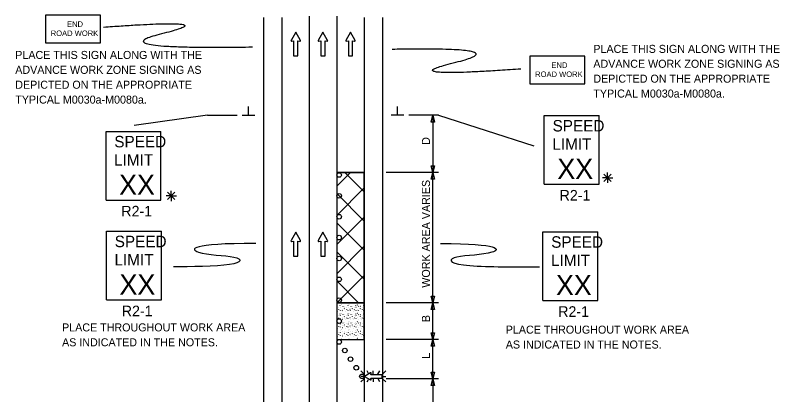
# Model space of a CAD drawing. Extents: x 16734 to 18479, y 5690 to 6925.
# Drawn here: x 16734 to 17402, y 6594 to 6925 of the extents above; entities that cross this region are included whole.
import ezdxf

# ---------------------------------------------------------------- set-up
doc = ezdxf.new("R2010")
doc.units = 0
for name, color, linetype in [('ALI_LEGAL_EX', 7, 'Continuous'), ('MT_SCRATCH_LEVEL_E', 7, 'Continuous'), ('PAVT_EDGE_EX', 7, 'Continuous'), ('TRAFFIC_SIGNS_PR', 7, 'Continuous'), ('TYPICAL_TEXT_DIMEN_PR', 7, 'Continuous')]:
    doc.layers.add(name, color=color, linetype=linetype)

msp = doc.modelspace()

# ---------------------------------------------------------------- linework, layer by layer
at = {"layer": 'ALI_LEGAL_EX'}
for p, q in [((16991.15, 6924.81), (16991.15, 6107.83)), ((17015.15, 6924.81), (17015.15, 6107.83))]:
    msp.add_line(p, q, dxfattribs=at)
for points in [[(16991.15, 6924.81), (16991.15, 6899.81)], [(17015.15, 6924.81), (17015.15, 6899.81)], [(16991.15, 6824.81), (16991.15, 6799.81)], [(17015.15, 6824.81), (17015.15, 6799.81)], [(16991.15, 6724.81), (16991.15, 6699.81)], [(17015.15, 6724.81), (17015.15, 6699.81)], [(16991.15, 6624.81), (16991.15, 6599.81)]]:
    msp.add_lwpolyline(points, dxfattribs=at)
at = {"layer": 'MT_SCRATCH_LEVEL_E'}
for p, q in [((16979.3, 6910.86), (16975.19, 6903.61)), ((16983.44, 6903.61), (16979.3, 6910.86)), ((17003, 6910.86), (16998.89, 6903.61)), ((17007.15, 6903.61), (17003, 6910.86)), ((17027.11, 6910.86), (17023, 6903.61)), ((17031.26, 6903.61), (17027.11, 6910.86)), ((16975.67, 6902.93), (16977.45, 6903.25)), ((16977.45, 6903.25), (16977.45, 6889.99)), ((16981.19, 6889.99), (16981.19, 6903.25)), ((16981.19, 6903.25), (16982.97, 6902.93)), ((16999.37, 6902.93), (17001.15, 6903.25)), ((17001.15, 6903.25), (17001.15, 6889.99)), ((17004.89, 6889.99), (17004.89, 6903.25)), ((17004.89, 6903.25), (17006.67, 6902.93)), ((17023.48, 6902.93), (17025.26, 6903.25)), ((17025.26, 6903.25), (17025.26, 6889.99)), ((17029, 6889.99), (17029, 6903.25)), ((17029, 6903.25), (17030.78, 6902.93)), ((16977.45, 6889.99), (16981.19, 6889.99)), ((17001.15, 6889.99), (17004.89, 6889.99)), ((17025.26, 6889.99), (17029, 6889.99)), ((16979.3, 6736.02), (16975.19, 6728.78)), ((16983.44, 6728.78), (16979.3, 6736.02)), ((17003, 6736.02), (16998.89, 6728.78)), ((17007.15, 6728.78), (17003, 6736.02)), ((16975.67, 6728.09), (16977.45, 6728.41)), ((16977.45, 6728.41), (16977.45, 6715.15)), ((16981.19, 6715.15), (16981.19, 6728.41)), ((16981.19, 6728.41), (16982.97, 6728.09)), ((16999.37, 6728.09), (17001.15, 6728.41)), ((17001.15, 6728.41), (17001.15, 6715.15)), ((17004.89, 6715.15), (17004.89, 6728.41)), ((17004.89, 6728.41), (17006.67, 6728.09)), ((16977.45, 6715.15), (16981.19, 6715.15)), ((17001.15, 6715.15), (17004.89, 6715.15))]:
    msp.add_line(p, q, dxfattribs=at)
for centre, start, end in [((16975.59, 6903.39), 150.42484, 279.96381), ((16983.04, 6903.39), 260.03619, 29.77312), ((16999.3, 6903.39), 150.42484, 279.96381), ((17006.74, 6903.39), 260.03619, 29.77312), ((17023.41, 6903.39), 150.42484, 279.96381), ((17030.85, 6903.39), 260.03619, 29.77312), ((16975.59, 6728.55), 150.42484, 279.96381), ((16983.04, 6728.55), 260.03619, 29.77312), ((16999.3, 6728.55), 150.42484, 279.96381), ((17006.74, 6728.55), 260.03619, 29.77312)]:
    msp.add_arc(centre, 0.463, start, end, dxfattribs=at)
at = {"layer": 'PAVT_EDGE_EX'}
for p, q in [((16951.15, 6923.54), (16951.15, 6107.83)), ((16967.15, 6923.54), (16967.15, 6107.83)), ((17039.15, 6923.54), (17039.15, 6107.83)), ((17055.15, 6923.54), (17055.15, 6107.83)), ((17039.15, 6788.15), (17015.15, 6788.15)), ((17015.15, 6788.15), (17039.15, 6788.15)), ((17015.15, 6776.25), (17027.06, 6788.15)), ((17039.15, 6771.35), (17022.34, 6788.15)), ((17039.15, 6674.43), (17039.15, 6788.15)), ((17015.15, 6750.8), (17039.15, 6774.8)), ((17039.15, 6745.89), (17015.15, 6769.89)), ((17015.15, 6725.34), (17039.15, 6749.34)), ((17039.15, 6720.43), (17015.15, 6744.43)), ((17015.15, 6699.89), (17039.15, 6723.89)), ((17039.15, 6694.98), (17015.15, 6718.98)), ((17015.15, 6674.43), (17039.15, 6698.43)), ((17034.24, 6674.43), (17015.15, 6693.52)), ((17015.15, 6674.43), (17039.15, 6674.43)), ((17015.15, 6674.43), (17039.15, 6674.43)), ((17039.15, 6674.43), (17015.15, 6674.43)), ((17015.15, 6674.43), (17015.15, 6674.43)), ((17016.08, 6674.07), (17016.13, 6674.19)), ((17016.65, 6670.75), (17016.7, 6670.67)), ((17016.7, 6668.54), (17016.75, 6668.46)), ((17018.1, 6671.88), (17018.15, 6671.99)), ((17018.18, 6670.61), (17018.23, 6670.53)), ((17018.86, 6672.84), (17018.92, 6672.76)), ((17019.6, 6672.81), (17019.65, 6672.73)), ((17019.82, 6668.82), (17019.87, 6668.94)), ((17020.47, 6671.43), (17020.52, 6671.35)), ((17021.75, 6669.69), (17021.8, 6669.61)), ((17021.92, 6671.58), (17021.97, 6671.69)), ((17022.97, 6674.07), (17023.02, 6674.19)), ((17023.54, 6670.75), (17023.59, 6670.67)), ((17023.59, 6668.54), (17023.64, 6668.46)), ((17024.99, 6671.88), (17025.04, 6671.99)), ((17025.07, 6670.61), (17025.12, 6670.53)), ((17025.75, 6672.84), (17025.8, 6672.76)), ((17026.49, 6672.81), (17026.54, 6672.73)), ((17026.71, 6668.82), (17026.76, 6668.94)), ((17027.36, 6671.43), (17027.41, 6671.35)), ((17028.64, 6669.69), (17028.69, 6669.61)), ((17028.81, 6671.58), (17028.86, 6671.69)), ((17029.85, 6674.07), (17029.91, 6674.19)), ((17030.42, 6670.75), (17030.48, 6670.67)), ((17030.47, 6668.54), (17030.53, 6668.46)), ((17031.88, 6671.88), (17031.93, 6671.99)), ((17031.96, 6670.61), (17032.01, 6670.53)), ((17032.64, 6672.84), (17032.69, 6672.76)), ((17033.38, 6672.81), (17033.43, 6672.73)), ((17033.6, 6668.82), (17033.65, 6668.94)), ((17034.24, 6671.43), (17034.3, 6671.35)), ((17035.52, 6669.69), (17035.57, 6669.61)), ((17035.69, 6671.58), (17035.75, 6671.69)), ((17036.74, 6674.07), (17036.8, 6674.19)), ((17037.31, 6670.75), (17037.36, 6670.67)), ((17037.36, 6668.54), (17037.41, 6668.46)), ((17038.76, 6671.88), (17038.81, 6671.99)), ((17038.84, 6670.61), (17038.89, 6670.53)), ((17039.15, 6642.37), (17039.15, 6674.43)), ((17016.08, 6666.79), (17016.13, 6666.9)), ((17016.65, 6663.46), (17016.7, 6663.39)), ((17017.98, 6667.96), (17017.99, 6667.85)), ((17018.1, 6664.59), (17018.15, 6664.71)), ((17018.18, 6663.32), (17018.23, 6663.25)), ((17018.86, 6665.55), (17018.92, 6665.47)), ((17019.6, 6665.52), (17019.65, 6665.44)), ((17020.01, 6667.62), (17020.06, 6667.54)), ((17020.47, 6664.14), (17020.52, 6664.06)), ((17021.75, 6662.4), (17021.8, 6662.33)), ((17021.79, 6668.29), (17021.84, 6668.4)), ((17021.92, 6664.29), (17021.97, 6664.41)), ((17022.97, 6666.79), (17023.02, 6666.9)), ((17023.54, 6663.46), (17023.59, 6663.39)), ((17024.87, 6667.96), (17024.88, 6667.85)), ((17024.99, 6664.59), (17025.04, 6664.71)), ((17025.07, 6663.32), (17025.12, 6663.25)), ((17025.75, 6665.55), (17025.8, 6665.47)), ((17026.49, 6665.52), (17026.54, 6665.44)), ((17026.9, 6667.62), (17026.95, 6667.54)), ((17027.36, 6664.14), (17027.41, 6664.06)), ((17028.64, 6662.4), (17028.69, 6662.33)), ((17028.68, 6668.29), (17028.73, 6668.4)), ((17028.81, 6664.29), (17028.86, 6664.41)), ((17029.85, 6666.79), (17029.91, 6666.9)), ((17030.42, 6663.46), (17030.48, 6663.39)), ((17031.76, 6667.96), (17031.77, 6667.85)), ((17031.88, 6664.59), (17031.93, 6664.71)), ((17031.96, 6663.32), (17032.01, 6663.25)), ((17032.64, 6665.55), (17032.69, 6665.47)), ((17033.38, 6665.52), (17033.43, 6665.44)), ((17033.78, 6667.62), (17033.84, 6667.54)), ((17034.24, 6664.14), (17034.3, 6664.06)), ((17035.52, 6662.4), (17035.57, 6662.33)), ((17035.56, 6668.29), (17035.62, 6668.4)), ((17035.69, 6664.29), (17035.75, 6664.41)), ((17036.74, 6666.79), (17036.8, 6666.9)), ((17037.31, 6663.46), (17037.36, 6663.39)), ((17038.64, 6667.96), (17038.66, 6667.85)), ((17038.76, 6664.59), (17038.81, 6664.71)), ((17038.84, 6663.32), (17038.89, 6663.25)), ((17016.08, 6659.5), (17016.13, 6659.62)), ((17016.65, 6656.18), (17016.7, 6656.1)), ((17016.7, 6661.26), (17016.75, 6661.18)), ((17017.98, 6660.68), (17017.99, 6660.56)), ((17018.1, 6657.31), (17018.15, 6657.42)), ((17018.18, 6656.04), (17018.23, 6655.96)), ((17018.86, 6658.27), (17018.92, 6658.19)), ((17019.6, 6658.24), (17019.65, 6658.16)), ((17019.82, 6661.53), (17019.87, 6661.65)), ((17020.01, 6660.34), (17020.06, 6660.26)), ((17020.47, 6656.86), (17020.52, 6656.78)), ((17021.79, 6661), (17021.84, 6661.12)), ((17021.92, 6657.01), (17021.97, 6657.12)), ((17022.97, 6659.5), (17023.02, 6659.62)), ((17023.54, 6656.18), (17023.59, 6656.1)), ((17023.59, 6661.26), (17023.64, 6661.18)), ((17024.87, 6660.68), (17024.88, 6660.56)), ((17024.99, 6657.31), (17025.04, 6657.42)), ((17025.07, 6656.04), (17025.12, 6655.96)), ((17025.75, 6658.27), (17025.8, 6658.19)), ((17026.49, 6658.24), (17026.54, 6658.16)), ((17026.71, 6661.53), (17026.76, 6661.65)), ((17026.9, 6660.34), (17026.95, 6660.26)), ((17027.36, 6656.86), (17027.41, 6656.78)), ((17028.68, 6661), (17028.73, 6661.12)), ((17028.81, 6657.01), (17028.86, 6657.12)), ((17029.85, 6659.5), (17029.91, 6659.62)), ((17030.42, 6656.18), (17030.48, 6656.1)), ((17030.47, 6661.26), (17030.53, 6661.18)), ((17031.76, 6660.68), (17031.77, 6660.56)), ((17031.88, 6657.31), (17031.93, 6657.42)), ((17031.96, 6656.04), (17032.01, 6655.96)), ((17032.64, 6658.27), (17032.69, 6658.19)), ((17033.38, 6658.24), (17033.43, 6658.16)), ((17033.6, 6661.53), (17033.65, 6661.65)), ((17033.78, 6660.34), (17033.84, 6660.26)), ((17034.24, 6656.86), (17034.3, 6656.78)), ((17035.56, 6661), (17035.62, 6661.12)), ((17035.69, 6657.01), (17035.75, 6657.12)), ((17036.74, 6659.5), (17036.8, 6659.62)), ((17037.31, 6656.18), (17037.36, 6656.1)), ((17037.36, 6661.26), (17037.41, 6661.18)), ((17038.64, 6660.68), (17038.66, 6660.56)), ((17038.76, 6657.31), (17038.81, 6657.42)), ((17038.84, 6656.04), (17038.89, 6655.96)), ((17016.08, 6652.22), (17016.13, 6652.33)), ((17016.65, 6648.89), (17016.7, 6648.82)), ((17016.7, 6653.97), (17016.75, 6653.89)), ((17017.98, 6653.39), (17017.99, 6653.28)), ((17018.1, 6650.02), (17018.15, 6650.14)), ((17018.18, 6648.75), (17018.23, 6648.68)), ((17018.86, 6650.98), (17018.92, 6650.9)), ((17019.6, 6650.95), (17019.65, 6650.87)), ((17019.82, 6654.25), (17019.87, 6654.37)), ((17020.01, 6653.05), (17020.06, 6652.97)), ((17020.47, 6649.57), (17020.52, 6649.49)), ((17021.75, 6655.12), (17021.8, 6655.04)), ((17021.79, 6653.72), (17021.84, 6653.84)), ((17021.92, 6649.72), (17021.97, 6649.84)), ((17022.97, 6652.22), (17023.02, 6652.33)), ((17023.54, 6648.89), (17023.59, 6648.82)), ((17023.59, 6653.97), (17023.64, 6653.89)), ((17024.87, 6653.39), (17024.88, 6653.28)), ((17024.99, 6650.02), (17025.04, 6650.14)), ((17025.07, 6648.75), (17025.12, 6648.68)), ((17025.75, 6650.98), (17025.8, 6650.9)), ((17026.49, 6650.95), (17026.54, 6650.87)), ((17026.71, 6654.25), (17026.76, 6654.37)), ((17026.9, 6653.05), (17026.95, 6652.97)), ((17027.36, 6649.57), (17027.41, 6649.49)), ((17028.64, 6655.12), (17028.69, 6655.04)), ((17028.68, 6653.72), (17028.73, 6653.84)), ((17028.81, 6649.72), (17028.86, 6649.84)), ((17029.85, 6652.22), (17029.91, 6652.33)), ((17030.42, 6648.89), (17030.48, 6648.82)), ((17030.47, 6653.97), (17030.53, 6653.89)), ((17031.76, 6653.39), (17031.77, 6653.28)), ((17031.88, 6650.02), (17031.93, 6650.14)), ((17031.96, 6648.75), (17032.01, 6648.68)), ((17032.64, 6650.98), (17032.69, 6650.9)), ((17033.38, 6650.95), (17033.43, 6650.87)), ((17033.6, 6654.25), (17033.65, 6654.37)), ((17033.78, 6653.05), (17033.84, 6652.97)), ((17034.24, 6649.57), (17034.3, 6649.49)), ((17035.52, 6655.12), (17035.57, 6655.04)), ((17035.56, 6653.72), (17035.62, 6653.84)), ((17035.69, 6649.72), (17035.75, 6649.84)), ((17036.74, 6652.22), (17036.8, 6652.33)), ((17037.31, 6648.89), (17037.36, 6648.82)), ((17037.36, 6653.97), (17037.41, 6653.89)), ((17038.64, 6653.39), (17038.66, 6653.28)), ((17038.76, 6650.02), (17038.81, 6650.14)), ((17038.84, 6648.75), (17038.89, 6648.68)), ((17015.15, 6642.37), (17039.15, 6642.37)), ((17015.15, 6642.37), (17039.15, 6642.37)), ((17016.08, 6644.93), (17016.13, 6645.05)), ((17016.7, 6646.69), (17016.75, 6646.61)), ((17017.98, 6646.11), (17017.99, 6645.99)), ((17018.1, 6642.74), (17018.15, 6642.85)), ((17018.86, 6643.7), (17018.92, 6643.62)), ((17019.6, 6643.67), (17019.65, 6643.59)), ((17019.82, 6646.97), (17019.87, 6647.08)), ((17020.01, 6645.77), (17020.06, 6645.69)), ((17021.75, 6647.84), (17021.8, 6647.76)), ((17021.79, 6646.43), (17021.84, 6646.55)), ((17021.92, 6642.44), (17021.97, 6642.56)), ((17022.97, 6644.93), (17023.02, 6645.05)), ((17023.59, 6646.69), (17023.64, 6646.61)), ((17024.87, 6646.11), (17024.88, 6645.99)), ((17024.99, 6642.74), (17025.04, 6642.85)), ((17025.75, 6643.7), (17025.8, 6643.62)), ((17026.49, 6643.67), (17026.54, 6643.59)), ((17026.71, 6646.97), (17026.76, 6647.08)), ((17026.9, 6645.77), (17026.95, 6645.69)), ((17028.64, 6647.84), (17028.69, 6647.76)), ((17028.68, 6646.43), (17028.73, 6646.55)), ((17028.81, 6642.44), (17028.86, 6642.56)), ((17029.85, 6644.93), (17029.91, 6645.05)), ((17030.47, 6646.69), (17030.53, 6646.61)), ((17031.76, 6646.11), (17031.77, 6645.99)), ((17031.88, 6642.74), (17031.93, 6642.85)), ((17032.64, 6643.7), (17032.69, 6643.62)), ((17033.38, 6643.67), (17033.43, 6643.59)), ((17033.6, 6646.97), (17033.65, 6647.08)), ((17033.78, 6645.77), (17033.84, 6645.69)), ((17035.52, 6647.84), (17035.57, 6647.76)), ((17035.56, 6646.43), (17035.62, 6646.55)), ((17035.69, 6642.44), (17035.75, 6642.56)), ((17036.74, 6644.93), (17036.8, 6645.05)), ((17037.36, 6646.69), (17037.41, 6646.61)), ((17038.64, 6646.11), (17038.66, 6645.99)), ((17038.76, 6642.74), (17038.81, 6642.85))]:
    msp.add_line(p, q, dxfattribs=at)
at = {"layer": 'TRAFFIC_SIGNS_PR'}
for p, q in [((17196.57, 6837.98), (17244.57, 6837.98)), ((17196.57, 6777.98), (17196.57, 6837.98)), ((17244.57, 6777.98), (17244.57, 6837.98)), ((16813.49, 6824.13), (16861.49, 6824.13)), ((16813.49, 6764.13), (16813.49, 6824.13)), ((16861.49, 6764.13), (16861.49, 6824.13)), ((17196.57, 6777.98), (17244.57, 6777.98)), ((16813.49, 6764.13), (16861.49, 6764.13)), ((16813.84, 6736.97), (16861.84, 6736.97)), ((16813.84, 6676.97), (16813.84, 6736.97)), ((16861.84, 6676.97), (16861.84, 6736.97)), ((17195.37, 6736.49), (17243.37, 6736.49)), ((17195.37, 6676.49), (17195.37, 6736.49)), ((17243.37, 6676.49), (17243.37, 6736.49)), ((16813.84, 6676.97), (16861.84, 6676.97)), ((17195.37, 6676.49), (17243.37, 6676.49)), ((17036.14, 6615.06), (17038.96, 6612.24)), ((17038.96, 6610.21), (17036.14, 6610.21)), ((17042.86, 6612.88), (17041.6, 6615.07)), ((17047.05, 6612.24), (17047.05, 6615.07)), ((17051.18, 6612.24), (17052.81, 6615.07)), ((17055.13, 6612.24), (17057.95, 6615.07)), ((17055.13, 6610.21), (17057.95, 6610.21)), ((17036.14, 6605.36), (17038.96, 6608.18)), ((17041.58, 6605.36), (17042.78, 6607.45)), ((17047.05, 6608.18), (17047.05, 6605.36)), ((17052.83, 6605.36), (17051.21, 6608.18)), ((17055.13, 6608.18), (17057.95, 6605.36))]:
    msp.add_line(p, q, dxfattribs=at)
for points in [[(16760.62, 6901.47), (16808.62, 6901.47), (16808.62, 6925.47), (16760.62, 6925.47)], [(17184.05, 6865.69), (17232.05, 6865.69), (17232.05, 6889.69), (17184.05, 6889.69)]]:
    msp.add_lwpolyline(points, close=True, dxfattribs=at)
for points in [[(17044.72, 6613.23), (17039.41, 6610.21), (17044.72, 6607.17)], [(17045.22, 6607.53), (17044.99, 6608.83), (17054.71, 6608.83), (17054.71, 6611.57), (17044.99, 6611.57), (17045.22, 6612.87)]]:
    msp.add_lwpolyline(points, dxfattribs=at)
for centre in [(17017.25, 6786.03), (17017.25, 6767.82), (17017.25, 6749.6), (17017.25, 6731.39), (17017.25, 6713.18), (17017.25, 6694.96), (17017.25, 6676.75), (17017.25, 6658.53), (17017.25, 6640.32), (17022.22, 6632.81), (17027.19, 6625.3), (17032.16, 6617.8), (17037.13, 6610.3)]:
    msp.add_circle(centre, 2, dxfattribs=at)
for centre, start, end in [((17044.89, 6612.93), 350.73078, 118.89165), ((17044.88, 6607.47), 241.48329, 9.95933)]:
    msp.add_arc(centre, 0.341, start, end, dxfattribs=at)
for points in [[(16811.3, 6915.15), (16919.8, 6923.28), (16805.9, 6895.7), (16941.37, 6897.87)], [(17175.98, 6878.54), (17060.76, 6870.3), (17174.67, 6897.89), (17063.65, 6895.72)]]:
    msp.add_open_spline(points, degree=2, dxfattribs=at)
at = {"layer": 'TYPICAL_TEXT_DIMEN_PR'}
for p, q in [((16938.03, 6838.15), (16938.03, 6845.94)), ((17068.28, 6838.15), (17068.28, 6845.94)), ((16902.15, 6838.15), (16837.93, 6829.31)), ((16902.15, 6838.15), (16928.15, 6838.15)), ((16932.4, 6838.15), (16943.65, 6838.15)), ((17073.9, 6838.15), (17062.65, 6838.15)), ((17104.15, 6838.15), (17078.15, 6838.15)), ((17097.58, 6832.29), (17099.15, 6838.15)), ((17099.15, 6838.15), (17100.72, 6832.29)), ((17099.15, 6838.15), (17099.15, 6788.15)), ((17104.15, 6838.15), (17187.33, 6811.59)), ((17099.15, 6832.29), (17097.58, 6832.29)), ((17100.72, 6832.29), (17099.15, 6832.29)), ((17099.15, 6788.15), (17097.58, 6794.02)), ((17097.58, 6794.02), (17099.15, 6794.02)), ((17099.15, 6794.02), (17100.72, 6794.02)), ((17100.72, 6794.02), (17099.15, 6788.15)), ((17104.15, 6788.15), (17058.45, 6788.15)), ((17097.58, 6782.29), (17099.15, 6788.15)), ((17099.15, 6782.29), (17097.58, 6782.29)), ((17099.15, 6674.43), (17099.15, 6788.15)), ((17099.15, 6788.15), (17100.72, 6782.29)), ((17100.72, 6782.29), (17099.15, 6782.29)), ((17251.89, 6783.65), (17247.36, 6783.65)), ((17248.7, 6786.84), (17255.08, 6780.47)), ((17255.08, 6786.84), (17248.7, 6780.47)), ((17251.89, 6783.65), (17251.89, 6788.11)), ((17251.89, 6783.65), (17255.08, 6783.65)), ((17251.89, 6783.65), (17256.37, 6783.65)), ((17251.89, 6783.65), (17251.89, 6779.15)), ((16873.67, 6771.01), (16867.29, 6764.64)), ((16867.3, 6771.01), (16873.67, 6764.64)), ((16870.48, 6767.83), (16870.48, 6772.28)), ((16870.48, 6767.83), (16865.95, 6767.83)), ((16870.48, 6767.83), (16873.67, 6767.83)), ((16870.48, 6767.83), (16874.96, 6767.83)), ((16870.48, 6767.83), (16870.48, 6763.33)), ((17099.15, 6674.43), (17097.58, 6680.29)), ((17097.58, 6680.29), (17099.15, 6680.29)), ((17099.15, 6680.29), (17100.72, 6680.29)), ((17100.72, 6680.29), (17099.15, 6674.43)), ((17104.15, 6674.43), (17058.45, 6674.43)), ((17097.58, 6668.57), (17099.15, 6674.43)), ((17099.15, 6668.57), (17097.58, 6668.57)), ((17099.15, 6642.37), (17099.15, 6674.43)), ((17099.15, 6674.43), (17100.72, 6668.57)), ((17100.72, 6668.57), (17099.15, 6668.57)), ((17104.15, 6642.37), (17058.45, 6642.37)), ((17099.15, 6642.37), (17097.58, 6648.23)), ((17097.58, 6648.23), (17099.15, 6648.23)), ((17097.58, 6636.51), (17099.15, 6642.37)), ((17099.15, 6648.23), (17100.72, 6648.23)), ((17100.72, 6648.23), (17099.15, 6642.37)), ((17099.15, 6608.18), (17099.15, 6642.37)), ((17099.15, 6642.37), (17100.72, 6636.51)), ((17099.15, 6636.51), (17097.58, 6636.51)), ((17100.72, 6636.51), (17099.15, 6636.51)), ((17099.15, 6608.18), (17097.58, 6614.04)), ((17097.58, 6614.04), (17099.15, 6614.04)), ((17099.15, 6614.04), (17100.72, 6614.04)), ((17100.72, 6614.04), (17099.15, 6608.18)), ((17104.15, 6608.18), (17058.45, 6608.18)), ((17097.58, 6602.32), (17099.15, 6608.18)), ((17099.15, 6602.32), (17097.58, 6602.32)), ((17099.15, 6608.18), (17099.15, 6558.18)), ((17099.15, 6608.18), (17100.72, 6602.32)), ((17100.72, 6602.32), (17099.15, 6602.32))]:
    msp.add_line(p, q, dxfattribs=at)
for points in [[(16944.43, 6726.31), (16886.55, 6726.31), (16886.55, 6716.09), (16932.86, 6716.09), (16932.86, 6706.35), (16886.71, 6705.91), (16872.49, 6705.88)], [(17105.7, 6726.29), (17158.78, 6726.02), (17158.34, 6716.09), (17112.48, 6716.09), (17112.48, 6705.88), (17192.46, 6705.88), (17192.46, 6705.88), (17192.46, 6705.88)]]:
    msp.add_open_spline(points, degree=3, dxfattribs=at)

# ---------------------------------------------------------------- texts
at = {"layer": 'TRAFFIC_SIGNS_PR'}
for s, height, p in [('END', 4.789, (16779.37, 6915.38)), ('ROAD WORK', 4.789, (16765.13, 6907.4)), ('PLACE THIS SIGN ALONG WITH THE', 7, (17239.42, 6892.66)), ('PLACE THIS SIGN ALONG WITH THE', 7, (16734.12, 6887.37)), ('END', 4.789, (17202.8, 6879.6)), ('ADVANCE WORK ZONE SIGNING AS', 7, (17239.42, 6879.66)), ('ADVANCE WORK ZONE SIGNING AS', 7, (16734.12, 6874.37)), ('ROAD WORK', 4.789, (17188.56, 6871.62)), ('DEPICTED ON THE APPROPRIATE', 7, (17239.42, 6866.66)), ('DEPICTED ON THE APPROPRIATE', 7, (16734.12, 6861.37)), ('TYPICAL M0030a-M0080a.', 7, (17239.42, 6853.66)), ('TYPICAL M0030a-M0080a.', 7, (16734.12, 6848.37)), ('SPEED', 10, (17203.78, 6824.06)), ('SPEED', 10, (16820.7, 6810.2)), ('LIMIT', 10, (17203.57, 6808.06)), ('LIMIT', 10, (16820.5, 6794.2)), ('XX', 17.538, (17207.96, 6782.68)), ('XX', 17.538, (16824.88, 6768.82)), ('R2-1', 9.3, (17209.91, 6763.69)), ('R2-1', 9.3, (16826.83, 6749.83)), ('SPEED', 10, (16821.05, 6723.05)), ('SPEED', 10, (17202.57, 6722.56)), ('LIMIT', 10, (16820.85, 6707.05)), ('LIMIT', 10, (17202.37, 6706.56)), ('XX', 17.538, (16825.23, 6681.67)), ('XX', 17.538, (17206.76, 6681.18)), ('R2-1', 9.3, (16827.19, 6662.68)), ('R2-1', 9.3, (17208.71, 6662.19)), ('PLACE THROUGHOUT WORK AREA', 7, (16775.03, 6649.51)), ('PLACE THROUGHOUT WORK AREA', 7, (17162.87, 6647.56)), ('AS INDICATED IN THE NOTES.', 7, (16775.03, 6636.51)), ('AS INDICATED IN THE NOTES.', 7, (17162.87, 6634.56))]:
    msp.add_text(s, height=height, dxfattribs=at).set_placement(p)
at = {"layer": 'TYPICAL_TEXT_DIMEN_PR'}
for s, p in [('D', (17096.59, 6812.37)), ('WORK AREA VARIES', (17096.59, 6687.65)), ('B', (17096.59, 6657.64)), ('L', (17096.59, 6625.67))]:
    msp.add_text(s, height=7, rotation=90, dxfattribs=at).set_placement(p)

doc.saveas('drawing.dxf')
